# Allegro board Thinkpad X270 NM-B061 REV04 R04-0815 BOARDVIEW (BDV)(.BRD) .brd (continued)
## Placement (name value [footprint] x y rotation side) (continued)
PC405  0.047U_0201_10V6-K  [C_0201]  129.2 97.97 90 bottom
PC406  1000P_0201_25V7-K  [C_0201]  129.79 100.7 270 bottom
PC407  2200P_0201_25V7-K  [C_0201]  129.13 100.29 180 bottom
PC408  0.1U_0201_25V6-K  [C_0201]  125.13 100.65 270 top
PC409  15P_0201_25V8-J  [C_0201]  124.77 98.89 0 top
PC410  1500P_0201_25V7-K  [C_0201]  125.94 99.49 270 top
PC411  270P_0201_25V7-M  [C_0201]  125.22 96.58 0 top
PC412  1000P_0201_25V7-K  [C_0201]  125.22 98.31 0 top
PC413  1000P_0201_25V7-K  [C_0201]  120.37 92.68 0 bottom
PC414  0.022U_0201_16V6-K  [C_0201]  119.37 98.72 270 top
PC416  3300P_0201_25V7-K  [C_0201]  120.89 93.28 90 bottom
PC417  470P_0201_25V7-K  [C_0201]  122.06 96.61 180 top
PC418  0.01U_0201_6.3V7-K  [C_0201]  120.77 98.28 0 top
PC419  1000P_0201_25V7-K  [C_0201]  118.78 97.76 90 bottom
PC420  820P_0201_25V7-K  [C_0201]  119.36 98.34 270 bottom
PC421  2200P_0201_25V7-K  [C_0201]  118.3 96.56 0 bottom
PC422  470P_0201_25V7-K  [C_0201]  118.28 95.4 0 bottom
PC423  15P_0201_25V8-J  [C_0201]  119.46 95.96 90 bottom
PC424  1000P_0201_25V7-K  [C_0201]  122.39 91.92 180 bottom
PC425  0.1U_0402_25V6-K  [C_0402]  120.76 99.02 0 top
PC426  1000P_0201_25V7-K  [C_0201]  123.6 91.91 180 bottom
PC427  1000P_0201_25V7-K  [C_0201]  123.02 92.51 90 bottom
PC428  15P_0201_25V8-J  [C_0201]  123.27 96.02 270 top
PC429  15N_0201_10V6-K  [C_0201]  122.68 94.79 0 top
PC430  0.047U_0402_25V7-K  [C_0402]  126.04 92.54 180 bottom
PC431  220P_0201_25V7K  [C_0201]  125.09 96 270 top
PC432  1000P_0201_25V7-K  [C_0201]  123.88 96.01 270 top
PC433  0.01U_0201_25V6-K  [C_0201]  130.08 97.95 90 bottom
PC434  1000P_0201_25V7-K  [C_0201]  125.41 91.81 0 bottom
PC435  10U_0603_25V6-M  [C_0603]  97.75 106.84 90 top
PC436  10U_0603_25V6-M  [C_0603]  96.45 106.84 90 top
PC437  0.1U_0402_25V6  [C_0402]  94.45 106.95 90 bottom
PC438  2200P_0402_25V7-K  [C_0402]  95.36 106.95 90 top
PC439  47P_0402_50V8-J  [C_0402]  95.36 106.95 90 bottom
PC440  22U_0603_6.3V6M  [C_0603]  89.95 83.06 270 top
PC441  22U_0603_6.3V6M  [C_0603]  87.3 76.62 0 top
PC442  22U_0603_6.3V6M  [C_0603]  87.25 81.72 0 top
PC443  22U_0603_6.3V6M  [C_0603]  89.93 80.72 270 top
PC444  22U_0603_6.3V6M  [C_0603]  86.26 77.94 180 top
PC445  22U_0603_6.3V6M  [C_0603]  86.26 81.75 180 top
PC446  22U_0603_6.3V6M  [C_0603]  87.25 82.99 0 top
PC447  22U_0603_6.3V6M  [C_0603]  86.66 75.27 0 top
PC448  22U_0603_6.3V6M  [C_0603]  87.27 79.16 0 top
PC449  0.22U_0402_16V6-M  [C_0402]  94.88 104.63 180 bottom
PC450  1U_0402_6.3V6-K  [C_0402]  88.35 100.39 0 bottom
PC451  1U_0402_6.3V6-K  [C_0402]  90.23 100.42 270 bottom
PC452  22U_0603_6.3V6M  [C_0603]  85.7 75.3 180 top
PC453  1500P_0402_50V7-K  [C_0402]  88.5 110.43 0 bottom
PC454  22U_0603_6.3V6M  [C_0603]  86.26 83.02 180 top
PC455  22U_0603_6.3V6M  [C_0603]  86.26 80.48 180 top
PC456  22U_0603_6.3V6M  [C_0603]  89.02 75.27 0 top
PC457  22U_0603_6.3V6M  [C_0603]  87.25 80.43 0 top
PC458  22U_0603_6.3V6M  [C_0603]  87.27 77.89 0 top
PC459  22U_0603_6.3V6M  [C_0603]  86.26 76.67 180 top
PC460  330U_D2_2V_R9M  [C_D2]  85.71 96.56 0 bottom
PC461  22U_0603_6.3V6M  [C_0603]  89.93 78.36 270 top
PC462  22U_0603_6.3V6M  [C_0603]  86.26 79.21 180 top
PC463  10U_0603_25V6-M  [C_0603]  59.45 105.56 270 top
PC464  10U_0603_25V6-M  [C_0603]  59.8 105.18 270 bottom
PC465  10U_0603_25V6-M  [C_0603]  58.58 105.17 270 bottom
PC466  10U_0603_25V6-M  [C_0603]  57.34 105.17 270 bottom
PC467  0.1U_0402_25V6  [C_0402]  60.84 104.91 270 bottom
PC468  2200P_0402_25V7-K  [C_0402]  60.54 105.04 270 top
PC469  47P_0402_50V8-J  [C_0402]  62.06 105.07 270 top
PC470  0.22U_0402_16V6-M  [C_0402]  59.91 107.59 0 bottom
PC471  1U_0402_6.3V6-K  [C_0402]  65.76 110.66 90 bottom
PC472  22U_0603_6.3V6M  [C_0603]  83.21 75.3 180 top
PC473  22U_0603_6.3V6M  [C_0603]  74.7 75.35 0 top
PC474  22U_0603_6.3V6M  [C_0603]  78.48 75.32 180 top
PC475  22U_0603_6.3V6M  [C_0603]  74.89 83.11 270 top
PC476  22U_0603_6.3V6M  [C_0603]  79.45 75.32 0 top
PC477  22U_0603_6.3V6M  [C_0603]  83.92 81.75 180 top
PC478  22U_0603_6.3V6M  [C_0603]  78.74 76.59 180 top
PC479  22U_0603_6.3V6M  [C_0603]  73.73 76.62 180 top
PC480  1U_0402_6.3V6-K  [C_0402]  67.26 109.56 0 bottom
PC481  22U_0603_6.3V6M  [C_0603]  73.73 82.97 180 top
PC482  22U_0603_6.3V6M  [C_0603]  79.7 77.86 0 top
PC483  22U_0603_6.3V6M  [C_0603]  78.74 79.13 180 top
PC484  22U_0603_6.3V6M  [C_0603]  83.92 80.48 180 top
PC485  22U_0603_6.3V6M  [C_0603]  79.7 80.4 0 top
PC486  680P_0402_50V7K  [C_0402]  65.41 102.04 180 bottom
PC487  330U_D2_2V_R9M  [C_D2]  74.2 98.92 180 bottom
PC488  22U_0603_6.3V6M  [C_0603]  79.7 76.59 0 top
PC489  22U_0603_6.3V6M  [C_0603]  74.89 78.41 270 top
PC490  22U_0603_6.3V6M  [C_0603]  83.89 77.91 180 top
PC491  22U_0603_6.3V6M  [C_0603]  83.89 79.18 180 top
PC492  22U_0603_6.3V6M  [C_0603]  73.73 79.16 180 top
PC493  22U_0603_6.3V6M  [C_0603]  78.74 82.94 180 top
PC494  22U_0603_6.3V6M  [C_0603]  76.13 78.41 270 top
PC495  22U_0603_6.3V6M  [C_0603]  79.7 79.13 0 top
PC496  22U_0603_6.3V6M  [C_0603]  73.71 80.45 180 top
PC497  22U_0603_6.3V6M  [C_0603]  79.7 82.94 0 top
PC498  10U_0603_25V6-M  [C_0603]  97.75 106.84 90 bottom
PC499  10U_0603_25V6-M  [C_0603]  96.45 106.84 90 bottom
PC500  33U_D2_25VM_R40M  [C_D2]  59.5 99.07 0 top
PC501  33U_D2_25VM_R40M  [C_D2]  102.3 104.81 270 top
PC502  33U_D2_25VM_R40M  [C_D2]  163.15 83.1 180 bottom
PC503  33U_D2_25VM_R40M  [C_D2]  58.33 99.17 0 bottom
PC506  22U_0603_6.3V6M  [C_0603]  83.92 83.02 180 top
PC507  22U_0603_6.3V6M  [C_0603]  78.74 77.86 180 top
PC508  22U_0603_6.3V6M  [C_0603]  69.57 97.4 0 top
PC510  22U_0603_6.3V6M  [C_0603]  73.71 77.86 180 top
PC511  22U_0603_6.3V6M  [C_0603]  76.13 83.11 270 top
PC512  22U_0603_6.3V6M  [C_0603]  76.13 80.75 270 top
PC513  22U_0603_6.3V6M  [C_0603]  74.89 80.75 270 top
PC514  22U_0603_6.3V6M  [C_0603]  83.89 76.64 180 top
PC515  22U_0603_6.3V6M  [C_0603]  79.7 81.67 0 top
PC516  22U_0603_6.3V6M  [C_0603]  78.74 80.4 180 top
PC517  22U_0603_6.3V6M  [C_0603]  78.74 81.67 180 top
PC522  10U_0603_25V6-M  [C_0603]  136.81 85.59 270 bottom
PC523  10U_0603_25V6-M  [C_0603]  137.75 86.94 90 bottom
PC524  0.1U_0402_25V6  [C_0402]  135.76 85.46 270 bottom
PC525  2200P_0402_25V7-K  [C_0402]  135.82 86.91 90 bottom
PC526  47P_0402_50V8-J  [C_0402]  136.68 86.91 90 bottom
PC527  0.22U_0402_16V6-M  [C_0402]  136.07 83.25 180 bottom
PC528  1U_0402_6.3V6-K  [C_0402]  130 80.26 0 bottom
PC529  1U_0402_6.3V6-K  [C_0402]  135.13 81.42 0 bottom
PC530  22U_0603_6.3V6M  [C_0603]  117 85.31 270 bottom
PC531  22U_0603_6.3V6M  [C_0603]  116.95 78.7 90 bottom
PC532  22U_0603_6.3V6M  [C_0603]  92.45 82.21 180 top
PC533  22U_0603_6.3V6M  [C_0603]  92.45 80.94 180 top
PC534  22U_0603_6.3V6M  [C_0603]  92.45 78.4 180 top
PC535  22U_0603_6.3V6M  [C_0603]  92.45 79.67 180 top
PC536  680P_0402_50V7K  [C_0402]  130.13 83.33 90 top
PC537  22U_0603_6.3V6M  [C_0603]  118.22 78.7 90 bottom
PC538  22U_0603_6.3V6M  [C_0603]  118.22 85.31 270 bottom
PC539  22U_0603_6.3V6M  [C_0603]  115.73 78.7 90 bottom
PC540  22U_0603_6.3V6M  [C_0603]  115.78 85.33 270 bottom
PC712  0.1U_0402_25V6  [C_0402]  140.42 101.1 270 bottom
PC713  10U_0603_25V6-M  [C_0603]  143.57 101.88 270 bottom
PC714  10U_0603_25V6-M  [C_0603]  142.35 101.88 270 bottom
PC715  2200P_0402_25V7-K  [C_0402]  139.56 101.1 270 bottom
PC716  2.2U_0603_10V6-K  [C_0603]  144.98 104.81 0 bottom
PC717  0.1U_0402_16V7-K  [C_0402]  151.19 99.48 0 bottom
PC718  0.1U_0402_6.3V7-K  [C_0402]  139.02 90.62 270 bottom
PC719  22U_0603_6.3V6M  [C_0603]  138.57 96.95 270 bottom
PC720  22U_0603_6.3V6M  [C_0603]  140.11 89.31 90 bottom
PC721  22U_0603_6.3V6M  [C_0603]  137.74 98.56 180 bottom
PC722  22U_0603_6.3V6M  [C_0603]  139.79 96.98 270 bottom
PC723  2200P_0402_25V7-K  [C_0402]  137.5 96.1 90 bottom
PC724  22U_0603_6.3V6M  [C_0603]  141.1 97.58 270 bottom
PC737  0.1U_0402_25V6-K  [C_0402]  133.38 73.62 90 bottom
PC738  10U_0603_10V  [C_0603]  134.43 73.58 90 bottom
PC739  0.1U_0402_25V6  [C_0402]  132.04 78.24 180 bottom
PC740  22U_0603_6.3V6-M  [C_0603]  134.65 78.62 90 bottom
PC741  22P_0402_50V  [C_0402]  133.51 71.56 0 bottom
PC743  22U_0603_6.3V6-M  [C_0603]  133.4 78.62 90 bottom
PC745  680P_0402_50V  [C_0402]  136.41 71.74 0 top
PC746  2200P_0402_25V7-K  [C_0402]  132.04 79.11 180 bottom
PC756  2200P_0402_25V7-K  [C_0402]  147.56 64.02 270 bottom
PC776  0.01U_0402_25V7-K  [C_0402]  148.52 104.56 90 bottom
PC783  2200P_0402_25V7-K  [C_0402]  158.45 64.17 180 bottom
PC784  10U_0603_10V  [C_0603]  158.72 63.13 180 bottom
PC785  22U_0603_6.3V6-M  [C_0603]  146.48 66.34 90 bottom
PC786  0.1U_0402_25V6  [C_0402]  147.55 66.89 90 bottom
PC787  680P_0402_50V7K  [C_0402]  143.06 97.17 90 bottom
PC788  68P_0402_50V8J  [C_0402]  138.67 101.1 270 bottom
PC789  0.1U_0603_25V7K  [C_0603]  151.85 96.43 270 bottom
PC790  47P_0402_50V8-J  [C_0402]  141.31 101.08 270 bottom
PC791  10U_0603_10V  [C_0603]  158.7 63.08 180 top
PC792  0.1U_0402_6.3V7-K  [C_0402]  152.16 100.37 180 bottom
PC793  22U_0603_6.3V6-M  [C_0603]  146.49 64.44 270 bottom
PC794  0.1U_0402_10V  [C_0402]  138.24 69.99 180 bottom
PC795  2200P_0402_25V7-K  [C_0402]  132.52 73.49 90 bottom
PC801  0.1U_0402_25V6-K  [C_0402]  158.43 64.12 180 top
PC802  680P_0402_50V  [C_0402]  156.68 64.2 180 bottom
PC803  22P_0402_50V  [C_0402]  160.54 66.38 90 bottom
PD1  -  [1SS400CMT2R_VMN2M2]  141.45 112.9 270 top
PD2  -  [1SS400CMT2R_VMN2M2]  143.94 112.9 90 top
PD4  -  [RB751V-40_SOD323-2]  109.63 104.84 0 top
PD5  -  [AZ5425-01F_DFN1006P2E2]  112.23 106.23 0 top
PD7  ESD9B5.0ST5G SOD-923  [DF2S6P8UFS_1-1L1A2]  231.99 107.26 90 top
PD8  ESD9B5.0ST5G SOD-923  [DF2S6P8UFS_1-1L1A2]  234.43 107.28 90 top
PD9  ESD9B5.0ST5G SOD-923  [DF2S6P8UFS_1-1L1A2]  235.49 107.31 90 top
PD10  -  [DAN222MGT2L_VMD3]  166.19 88.79 90 top
PD11  -  [DAN222MGT2L_VMD3]  149.23 112.51 270 top
PD12  -  [DAN222MGT2L_VMD3]  184.08 63.19 180 bottom
PD13  -  [DAN222MGT2L_VMD3]  264.47 97.1 270 top
PD14  -  [DAN222MGT2L_VMD3]  177.91 84.01 0 bottom
PD15  -  [DAN222MGT2L_VMD3]  180.13 64.44 0 bottom
PD16  -  [DAN222MGT2L_VMD3]  182.48 62.12 0 bottom
PD17  -  [DAN222MGT2L_VMD3]  263.52 95.8 0 top
PD18  -  [DAN222MGT2L_VMD3]  261.84 95.8 0 top
PD30  EDZVT2R5.1B  [RB520SM-30T2R_EMD2-2]  158.01 87.49 0 top
PD31  -  [DAN222MGT2L_VMD3]  162.74 87.06 180 top
PD32  RB161SS-30T2R  [RB521CS-30GT2RA_VMN2-2]  162.38 91.91 90 top
PD102  RB521CM_30  [RB521CS-30GT2RA_VMN2-2]  191.03 66.22 90 top
PD301  RB521CM_30  [RB521CS-30GT2RA_VMN2-2]  120.11 61.1 0 bottom
PD701  RB751V-40  [RB751V-40_SOD323-2]  140.12 69.38 180 top
PF2  7A_24V_0429007.WRMLHF  [F_S1206-H-5P0A]  130.87 111.95 0 top
PF3  10A_32V_0501010.WR  [F_TR-3216FF10-R]  189.87 60.94 90 bottom
PF4  10A_32V_0501010.WR  [F_TR-3216FF10-R]  226.81 101.49 180 top
PF5  0.5A_32V_ERBRD0R50X  [F_ERBRD0R50X]  166.24 91.08 270 top
PF6  0.5A_32V_ERBRD0R50X  [F_ERBRD0R50X]  146.21 112.86 0 top
PF7  0.5A_32V_ERBRD0R50X  [F_ERBRD0R50X]  186.81 62.39 180 bottom
PF8  0.5A_32V_ERBRD0R50X  [F_ERBRD0R50X]  261.14 96.77 0 top
PF9  0.5A_32V_ERBRD0R50X  [F_ERBRD0R50X]  176.59 85.97 270 bottom
PF11  0.5A_32V_ERBRD0R50X  [F_ERBRD0R50X]  156.24 96.54 0 top
PJ1  MOLEX_78048-0543  [MOLEX_78048-0543_5P-T]  109.91 103.98 90 bottom
PJ2  JST_SM05BLBTAKSTDN2T-HF  [JST_SM05BLBTAKSTDN2T-HF_5P-T]  189.18 58.93 180 bottom
PJ3  FOX_BBP27BY-B4801-7H  [FOX_BBP27BY-B4801-7H_7P-T]  225.6 104.31 0 bottom
PJ4  -  [JUMP_43X79]  14.53 71.9 180 bottom
PJ201  -  [JUMP_43X79]  174.33 84.21 90 bottom
PJ202  -  [JUMP_43X79]  145.55 85.08 0 bottom
PJ203  -  [JUMP_43X118]  145.14 76.2 270 bottom
PJ204  -  [JUMP_43X118]  176.54 70.2 90 bottom
PJ301  -  [JUMP_43X79]  125.59 57.59 180 bottom
PJ302  -  [JUMP_43X118]  88.78 58.76 270 top
PJ303  -  [JUMP_43X118]  91.4 59.73 0 top
PJ304  -  [JUMP_43X39]  121.09 68.42 0 bottom
PJ701  -  [JUMP_43X79]  136.53 100.7 0 bottom
PJ702  -  [JUMP_43X118]  135.3 95.95 0 bottom
PJ703  -  [JUMP_43X118]  135.3 91.88 0 bottom
PJ711  -  [JUMP_43X79]  130.84 76.34 0 bottom
PJ712  -  [JUMP_43X79]  131.51 73.34 180 bottom
PJ715  -  [JUMP_43X79]  160.05 63.99 0 bottom
PJ716  -  [JUMP_43X79]  144.13 65.26 0 bottom
PL1  1.0UH_DFE252010F-100M=P2_20%  [CYNTE_HMMB25201T-1R0MSR_2P]  158.09 93.01 0 top
PL101  2.2UH_CMLE063T-2R2MS_10A_20%  [CYNTE_PCMB063T-2R2MS_2P]  189.37 77.2 90 bottom
PL102  BLM18KG300TN1D  [TDK_MPZ1608S300AT_2P]  147.71 109.8 0 top
PL103  BLM18KG300TN1D  [TDK_MPZ1608S300AT_2P]  147.7 108.53 0 top
PL201  2.2UH_PCMB063T-2R2MS_8A_20%  [CYNTE_PCMB063T-2R2MS_2P]  168.51 71.92 90 bottom
PL202  2.2UH_PCMB063T-2R2MS_8A_20%  [CYNTE_PCMB063T-2R2MS_2P]  150.71 77.35 270 bottom
PL301  1UH_PCMC063T-1R0MN_11A_20%  [CYNTE_PCMC063T-1R0MN_2P]  111.77 58.13 270 bottom
PL401  0.15UH_CMLE063T-R15MS0R907_38A_20%  [CYNTE_PCME063T-R15MS0R907_2P]  84.33 107.01 270 bottom
PL402  0.15UH_CMLE063T-R15MS0R907_38A_20%  [CYNTE_PCME063T-R15MS0R907_2P]  69.57 105.3 0 bottom
PL404  0.47UH_PCMB063T-R47MS3R675_18A_20%  [CYNTE_PCMB063T-R47MS3R675_2P]  126.96 82.92 180 bottom
PL405  BLM18KG300TN1D  [TDK_MPZ1608S300AT_2P]  96.91 103.85 90 bottom
PL406  BLM18KG300TN1D  [TDK_MPZ1608S300AT_2P]  98.13 103.85 90 bottom
PL407  BLM18KG300TN1D  [TDK_MPZ1608S300AT_2P]  59.42 108.38 270 top
PL408  BLM18KG300TN1D  [TDK_MPZ1608S300AT_2P]  58.28 109 270 bottom
PL410  BLM18KG300TN1D  [TDK_MPZ1608S300AT_2P]  138.03 83.87 90 bottom
PL702  1.0UH_PCMC063T-1R0MN_11A_20%  [CYNTE_PCMB063T-1R0MS_2P]  149.18 93.13 180 bottom
PL703  1UH_PH041H-1R0MS_3.8A_20%  [CYNTE_PH041H-1R0MS_2P]  139.76 77.61 180 bottom
PL704  1UH_PH041H-1R0MS_3.8A_20%  [CYNTE_PH041H-1R0MS_2P]  152.82 65.54 180 bottom
PQ2  AON7409  [SI7121DN-T1-GE3_POWERPAK-8-5]  159.48 100.73 270 top
PQ5  LSK3541G1ET2L  [2SK3541_VMT3]  133.43 106.98 180 top
PQ6  AON7409  [SI7121DN-T1-GE3_POWERPAK-8-5]  135.71 112.51 270 top
PQ7  AON7409  [SI7121DN-T1-GE3_POWERPAK-8-5]  142.97 109.56 90 top
PQ8  -  [DTA014EMT2L_VMT3]  131.56 106.93 180 top
PQ9  LSK3541G1ET2L  [2SK3541_VMT3]  130.12 107.92 270 top
PQ10  LSK3541G1ET2L  [2SK3541_VMT3]  135.59 107 180 top
PQ11  NTJD5121NT1G 2N SC88-6  [2N7002KDWH_SOT363-6]  108.38 108.28 180 top
PQ12  AON7466  [SIS406DN-T1-GE3_PAK1212-8-5]  19.22 73.46 90 top
PQ13  AON7466  [SIS406DN-T1-GE3_PAK1212-8-5]  15.71 69.01 0 top
PQ14  AON6380  [TPCA8059-H_PPAK56-8-5]  191.03 75.99 180 top
PQ15  -  [2N7002WT1G_SC-70-3]  19.28 71.69 180 bottom
PQ17  AON7466  [SIS406DN-T1-GE3_PAK1212-8-5]  187.71 63.58 180 bottom
PQ18  AON7409  [SI7121DN-T1-GE3_POWERPAK-8-5]  189.48 65.11 90 bottom
PQ19  AON7466  [SIS406DN-T1-GE3_PAK1212-8-5]  224.39 99.41 180 top
PQ20  AON7409  [SI7121DN-T1-GE3_POWERPAK-8-5]  226.51 98.44 270 top
PQ21  -  [SSM6J402TU_UF6]  181.61 64.22 90 bottom
PQ22  -  [DTC015EMT2L_VMT3]  178.19 66.01 0 bottom
PQ23  -  [SSM6J402TU_UF6]  262.08 93.61 270 top
PQ24  -  [DTC015EMT2L_VMT3]  262.08 90.87 270 top
PQ37  -  [AON6248_DFN8-5]  18.31 66.77 180 top
PQ41  LSK3541G1ET2L  [2SK3541_VMT3]  137.79 108.83 90 top
PQ42  -  [2SCR512P5T100_MPT3]  255.2 89.2 90 top
PQ103  AON7409  [SI7121DN-T1-GE3_POWERPAK-8-5]  203.54 93.15 270 top
PQ104  LSK3541G1ET2L  [2SK3541_VMT3]  199.77 88.2 270 top
PQ105  LSK3541G1ET2L  [2SK3541_VMT3]  203.63 66.66 270 top
PQ106  LSK3541G1ET2L  [2SK3541_VMT3]  205.38 69.51 270 top
PQ107  LSK3541G1ET2L  [2SK3541_VMT3]  202.23 68.26 90 top
PQ108  AON7409  [SI7121DN-T1-GE3_POWERPAK-8-5]  196.56 84.7 270 top
PQ109  LSK3541G1ET2L  [2SK3541_VMT3]  197.55 81.06 90 top
PQ110  AON6380  [TPCA8059-H_PPAK56-8-5]  187.33 74.23 0 bottom
PQ111  AON6380  [TPCA8059-H_PPAK56-8-5]  181.01 80.89 0 bottom
PQ112  AON7380  [SIS406DN-T1-GE3_PAK1212-8-5]  191.96 85.47 270 top
PQ113  AON7380  [SIS406DN-T1-GE3_PAK1212-8-5]  190.11 87.44 180 top
PQ201  AON7410 1N DFN  [AON7408L_DFN8-5]  170.56 80.66 90 bottom
PQ202  AON7410 1N DFN  [AON7408L_DFN8-5]  149.69 79.98 180 bottom
PQ203  AON7534 1N DFN  [AON7408L_DFN8-5]  166.23 83.46 0 bottom
PQ204  AON7534 1N DFN  [AON7408L_DFN8-5]  151.5 82.78 0 bottom
PQ301  AON7410 1N DFN  [AON7408L_DFN8-5]  116.01 56.73 90 bottom
PQ302  AON7534 1N DFN  [AON7408L_DFN8-5]  118.81 55.05 270 bottom
PR1  200K_0201_5%  [R_0201]  158.04 97.58 270 top
PR2  100K_0201_5%  [R_0201]  159.23 96.97 180 top
PR3  100_0201_5%  [R_0201]  158.65 97.55 0 top
PR6  24_1210_1%  [R_1210]  263.07 88.41 0 top
PR7  20_1210_1%  [R_1210]  258.17 90.85 270 top
PR8  200K_0201_5%  [R_0201]  134.65 109.42 90 top
PR9  100_0201_5%  [R_0201]  135.3 109.33 0 top
PR10  100_0201_5%  [R_0201]  144.58 112.06 180 top
PR11  270_0201_5%  [R_0201]  131.62 106.21 0 top
PR12  200K_0201_5%  [R_0201]  144.58 111.5 180 top
PR13  100K_0201_5%  [R_0201]  134.65 106.21 180 top
PR14  470K_0402_5%  [R_0402]  136.86 108.17 270 top
PR15  750_0201_1%  [R_0201]  109.28 106.12 90 top
PR16  0_0201_5%  [R0201_SHORT]  109.25 108.27 270 top
PR17  10K_0402_1%  [R_0402]  110.17 106.23 0 top
PR18  1M_0201_5%  [R_0201]  105.61 108.6 0 top
PR19  1M_0201_5%  [R_0201]  106.19 108.01 180 top
PR20  1M_0201_5%  [R_0201]  19.5 68.34 180 top
PR21  0_0201_5%  [R_0201]  19.5 68.97 180 top
PR22  0_0201_5%  [R_0201]  20.91 76.08 180 top
PR23  1M_0201_5%  [R_0201]  21.03 75.46 270 top
PR24  750_0603_1%  [R_0603]  253.44 87.11 0 top
PR25  0.005_1206_1%  [R_1206]  20.66 72.42 0 top
PR26  6.19K_0201_1%  [R_0201]  182.61 61.15 180 bottom
PR27  100_0201_5%  [R_0201]  186.57 60.6 90 bottom
PR28  100_0201_5%  [R_0201]  185.96 60.6 90 bottom
PR29  510K_0201_5%  [R_0201]  188.94 65.14 180 top
PR30  100_0201_5%  [R_0201]  189.26 65.79 90 top
PR31  100K_0201_5%  [R_0201]  184.57 64.9 270 bottom
PR32  150K_0201_5%  [R_0201]  190.13 65.14 180 top
PR33  6.19K_0201_1%  [R_0201]  236.33 106.83 90 top
PR34  100_0201_5%  [R_0201]  232.88 106.83 90 top
PR35  100_0201_5%  [R_0201]  233.54 106.83 90 top
PR36  510K_0201_5%  [R_0201]  225.29 95.21 180 top
PR37  100_0201_5%  [R_0201]  225.9 95.21 0 top
PR38  100K_0201_5%  [R_0201]  221.17 98.98 90 top
PR39  150K_0201_5%  [R_0201]  226.49 94.6 180 top
PR40  470K_0201_5%  [R_0201]  183.03 67.3 0 bottom
PR41  100_0201_5%  [R_0201]  182.15 66.4 180 bottom
PR42  4.7K_0201_5%  [R_0201]  181.55 66.98 0 bottom
PR43  470K_0201_5%  [R_0201]  264.24 91.17 0 top
PR44  100_0201_5%  [R_0201]  263.61 91.17 180 top
PR45  4.7K_0201_5%  [R_0201]  263.02 90.56 0 top
PR46  2K_0402_5%  [R_0402]  4.57 66.19 90 bottom
PR77  2.7K_0805_5%  [R_0805]  156.69 90.71 270 top
PR78  56.2K_0201_1%  [R_0201]  161.65 87.85 180 top
PR79  10K_0201_1%  [R_0201]  160.43 88.45 180 top
PR82  169K_0402_1%  [R_0402]  15.55 74.36 0 bottom
PR83  24.3K_0402_1%  [R_0402]  22.02 73.37 0 bottom
PR84  3.9K_0402_5%  [R_0402]  15.55 73.47 0 bottom
PR87  100K_0402_1%  [R_0402]  2.54 64.3 0 bottom
PR88  100K_0402_1%  [R_0402]  3.58 66.08 180 bottom
PR89  27.4K_0402_1%  [R_0402]  2.47 63.42 0 bottom
PR90  0_0402_5%  [R_0402]  2.54 65.19 0 bottom
PR91  0_0201_5%  [R0201_SHORT]  21.65 70.52 90 top
PR92  0_0201_5%  [R0201_SHORT]  22.21 70.52 90 top
PR95  0.005_1206_1%  [R_1206]  12.37 64.88 270 top
PR96  47_0402_5%  [R_0402]  11.05 61.71 0 bottom
PR97  10_0402_1%  [R_0402]  6.35 67.12 270 bottom
PR98  100K_0402_1%  [R_0402]  7.23 66.21 90 bottom
PR99  26.1K_0402_1%  [R_0402]  5.45 67.1 270 bottom
PR101  100K_0201_1%  [R_0201]  203.62 72.14 270 top
PR102  0_0603_5%  [R_0603]  195.61 68.99 90 top
PR103  0_0603_5%  [R_0603]  194.39 68.99 90 top
PR133  10_0201_1%  [R_0201]  198.43 71.71 270 top
PR134  40.2K_0201_1%  [R_0201]  203.56 77.95 270 top
PR135  100K_0201_1%  [R_0201]  201.39 68.19 180 top
PR136  10_0603_5%  [R_0603]  203.32 69.68 180 top
PR137  0_0402_5%  [R_0402]  195.79 77.99 90 top
PR138  10_0201_1%  [R_0201]  197.44 71.71 270 top
PR139  0_0201_5%  [R_0201]  200.33 80.71 0 top
PR140  10K_0201_5%  [R_0201]  200.21 69.35 90 top
PR141  0_0201_5%  [R_0201]  202.61 73.06 0 top
PR142  75_0201_5%  [R_0201]  203.76 74 180 top
PR144  20K_0201_1%  [R_0201]  201.6 79.34 0 top
PR145  100K_0201_1%  [R_0201]  201.01 79.18 180 top
PR146  0_0402_5%  [R_0402]  204.17 75.68 180 top
PR147  280K_0201_1%  [R_0201]  201.39 68.77 180 top
PR148  0_0402_5%  [R_0402]  204.17 74.76 180 top
PR149  0_0402_5%  [R_0402]  194.39 74.41 270 top
PR150  20K_0201_1%  [R_0201]  205.36 73.06 180 top
PR151  0.01_1206_LE_1%  [R_1206_LE]  208 92.06 0 top
PR152  100K_0201_1%  [R_0201]  204.95 77.66 0 top
PR153  56_0402_5%  [R_0402]  179.56 79.46 90 bottom
PR154  71.5K_0201_1%  [R_0201]  200.43 78.63 0 top
PR155  0_0201_5%  [R_0201]  200.33 80.15 0 top
PR156  56_0402_5%  [R_0402]  189.32 87.03 0 bottom
PR157  0_0201_5%  [R_0201]  202.35 72.14 0 top
PR158  0.01_1206_LE_1%  [R_1206_LE]  182.6 70.93 0 bottom
PR160  0_0402_5%  [R_0402]  193.57 74.41 270 bottom
PR161  0_0402_5%  [R_0402]  192.27 82.12 180 top
PR162  0_0201_5%  [R_0201]  203.81 78.6 0 top
PR163  100K_0201_5%  [R_0201]  204.24 70.65 0 top
PR164  100K_0201_5%  [R_0201]  205.37 68.35 270 top
PR165  1K_0201_1%  [R_0201]  196.72 71.71 270 top
PR166  0_0201_5%  [R_0201]  203.74 76.72 180 top
PR167  1M_0201_5%  [R_0201]  204.14 67.78 0 top
PR168  10K_0201_5%  [R_0201]  200.78 69.37 90 top
PR169  510K_0201_5%  [R_0201]  195.48 82 270 top
PR170  0_0402_5%  [R_0402]  203.31 89.83 0 top
PR171  100_0201_5%  [R_0201]  196.13 81.57 0 top
PR172  150K_0201_5%  [R_0201]  196.72 80.99 180 top
PR179  1K_0201_5%  [R_0201]  200.57 88.65 270 top
PR190  14.3K_0201_1%  [R_0201]  204.95 77.08 0 top
PR196  0_0201_5%  [R_0201]  198.23 68.67 270 top
PR197  0_0201_5%  [R_0201]  197.66 68.67 270 top
PR208  0_0402_5%  [R0402_SHORT]  156.02 75.55 90 bottom
PR209  0_0402_5%  [R0402_SHORT]  163.08 76.54 270 bottom
PR210  150K_0201_1%  [R_0201]  161.63 70.83 180 bottom
PR211  130K_0201_1%  [R_0201]  157.59 70.8 0 bottom
PR212  4.7_0603_5%  [R_0603]  167.98 81.89 270 top
PR213  4.7_0603_5%  [R_0603]  154.97 80.17 270 bottom
PR214  0_0201_5%  [R0201_SHORT]  158.81 70.8 90 bottom
PR215  0_0201_5%  [R0201_SHORT]  160.44 70.83 90 bottom
PR216  200_0402_1%  [R_0402]  163.12 74 0 bottom
PR217  15K_0201_1%  [R_0201]  163.12 73.16 0 bottom
PR218  13.7K_0201_1%  [R_0201]  156.27 72.83 180 bottom
PR219  200K_0201_1%  [R_0201]  158.18 71.39 180 bottom
PR220  100K_0201_1%  [R_0201]  161.63 71.41 180 bottom
PR221  0_0201_5%  [R0201_SHORT]  155.67 73.47 0 bottom
PR222  0_0201_5%  [R0201_SHORT]  156.26 74.05 180 bottom
PR301  0_0201_5%  [R0201_SHORT]  120.81 64.81 0 bottom
PR302  0_0201_5%  [R_0201]  120.57 62.45 0 bottom
PR303  64.9K_0201_1%  [R_0201]  124.52 65.39 180 top
PR304  1K_0201_5%  [R_0201]  123.94 66 0 top
PR305  100K_0201_1%  [R_0201]  121.29 65.65 0 bottom
PR306  0_0201_5%  [R0201_SHORT]  120.57 61.89 0 bottom
PR307  13K_0201_1%  [R_0201]  128 65.32 0 top
PR308  25.5K_0201_1%  [R_0201]  128.94 63.97 90 bottom
PR309  0_0402_5%  [R0402_SHORT]  121.93 61.56 270 bottom
PR311  4.7_0603_5%  [R_0603]  117.38 51.5 180 bottom
PR312  0_0402_5%  [R0402_SHORT]  126.15 64.66 180 top
PR401  100_0201_5%  [R_0201]  131.59 96.77 180 bottom
PR402  1K_0402_5%  [R_0402]  118.35 101.64 270 bottom
PR403  2_0603_5%  [R_0603]  118.36 102.73 0 bottom
PR404  47_0201_5%  [R_0201]  131.58 95.65 180 bottom
PR405  10K_0201_5%  [R_0201]  129.31 93.08 180 bottom
PR406  0_0201_5%  [R0201_SHORT]  129.32 93.66 180 bottom
PR407  51_0201_5%  [R_0201]  129.85 95.65 180 bottom
PR408  10_0201_5%  [R_0201]  129.86 96.81 180 bottom
PR409  0_0201_5%  [R0201_SHORT]  129.86 96.24 180 bottom
PR410  75_0201_5%  [R_0201]  129.53 97.38 0 bottom
PR411  3K_0402_1%  [R_0402]  130.89 97.91 90 bottom
PR412  20K_0402_1%  [R_0402]  121.94 94.82 90 top
PR413  10K_0201_1%  [R_0201]  131.65 98.14 90 bottom
PR414  2.21K_0201_1%  [R_0201]  129.18 100.87 180 bottom
PR415  1K_0201_1%  [R_0201]  129.14 99.73 180 bottom
PR416  0_0201_5%  [R0201_SHORT]  125.72 100.66 270 top
PR417  61.9K_0201_1%  [R_0201]  93.54 100.57 180 bottom
PR418  2.49K_0201_1%  [R_0201]  124.77 99.48 0 top
PR419  35.7K_0201_1%  [R_0201]  125.22 97.73 0 top
PR420  68.1K_0201_1%  [R_0201]  125.22 97.15 0 top
PR421  7.5K_0201_1%  [R_0201]  118.72 98.73 180 top
PR423  10_0201_1%  [R_0201]  118.14 98.11 0 top
PR424  1K_0201_1%  [R_0201]  120.3 93.28 90 bottom
PR425  24.9K_0201_1%  [R_0201]  122.07 97.21 180 top
PR427  68K_0402_1%  [R_0402]  117.99 98.49 180 bottom
PR428  562_0201_1%  [R_0201]  119.45 94.77 90 bottom
PR429  73.2K_0201_1%  [R_0201]  118.14 97.17 180 bottom
PR430  165K_0201_1%  [R_0201]  117.55 97.76 0 bottom
PR432  4.75K_0201_1%  [R_0201]  118.86 95.97 180 bottom
PR433  12.4K_0201_1%  [R_0201]  119.36 97.17 180 bottom
PR434  49.9_0201_1%  [R_0201]  118.86 94.78 180 bottom
PR435  2.8K_0201_1%  [R_0201]  122.43 92.54 90 bottom
PR436  0_0201_5%  [R0201_SHORT]  119.33 99.99 180 bottom
PR437  61.9K_0201_1%  [R_0201]  62.4 111.9 180 bottom
PR438  1K_0201_1%  [R_0201]  123.6 92.51 90 bottom
PR439  3K_0402_1%  [R_0402]  127.47 92.54 270 bottom
PR440  10K_0201_1%  [R_0201]  126.76 92.54 270 bottom
PR441  1.5K_0201_1%  [R_0201]  122.68 96.02 270 top
PR442  31.6K_0201_1%  [R_0201]  124.46 96 270 top
PR443  110K_0201_1%  [R_0201]  125.69 95.99 270 top
PR444  24K_0201_5%  [R_0201]  121.57 101.43 0 top
PR445  24K_0201_5%  [R_0201]  121.57 100.85 0 top
PR446  49.9K_0201_1%  [R_0201]  122.74 100.65 270 top
PR447  100K_0201_1%  [R_0201]  123.33 100.05 90 top
PR448  15.8K_0201_1%  [R_0201]  123.91 100.65 270 top
PR449  10K_0201_1%  [R_0201]  124.55 100.65 270 top
PR450  0_0201_5%  [R0201_SHORT]  119.21 99.33 180 bottom
PR451  2_0603_5%  [R_0603]  88.66 101.43 0 bottom
PR452  2.21K_0201_1%  [R_0201]  127.48 101.91 180 bottom
PR453  3.9_0402_1%  [R_0402]  93.96 103.64 0 bottom
PR455  4.7_0603_5%  [R_0603]  87.46 110.4 270 bottom
PR456  3.9_0402_1%  [R_0402]  60.89 108.8 180 bottom
PR457  2_0603_5%  [R_0603]  68.11 111.09 180 bottom
PR461  4.7_0603_5%  [R_0603]  66.33 102.12 0 bottom
PR462  0_0402_5%  [R0402_SHORT]  119.54 100.9 180 top
PR463  0_0201_5%  [R0201_SHORT]  79.75 103.18 270 bottom
PR464  0_0201_5%  [R0201_SHORT]  80.35 103.18 270 bottom
PR465  0_0201_5%  [R0201_SHORT]  72.2 109.64 90 bottom
PR466  0_0201_5%  [R0201_SHORT]  72.78 109.64 90 bottom
PR467  0_0201_5%  [R0201_SHORT]  124.65 86.72 90 bottom
PR468  0_0201_5%  [R0201_SHORT]  123 86.77 90 bottom
PR469  2_0603_5%  [R_0603]  130.33 80.92 180 top
PR470  3.9_0402_1%  [R_0402]  135.15 82.31 0 bottom
PR473  2.8K_0201_1%  [R_0201]  121.81 92.55 90 bottom
PR474  0_0201_5%  [R_0201]  129.87 94.5 180 bottom
PR475  0_0201_5%  [R0201_SHORT]  129.26 95.08 0 bottom
PR476  4.7_0603_5%  [R_0603]  129.06 83.21 90 top
PR477  0_0201_5%  [R0201_SHORT]  128.7 92.5 270 bottom
PR708  0_0201_5%  [R_0201]  147.75 104.28 180 bottom
PR709  0_0402_5%  [R0402_SHORT]  148.03 97.57 0 bottom
PR718  0_0201_5%  [R0201_SHORT]  138.95 70.71 270 bottom
PR721  10K_0201_1%  [R_0201]  134.97 70.78 0 bottom
PR722  4.7_0603_5%  [R_0603]  138.22 71.59 0 top
PR723  20K_0201_1%  [R_0201]  133.8 70.78 0 bottom
PR724  31.6K_0201_1%  [R_0201]  159.72 66.8 90 bottom
PR738  100K_0201_5%  [R_0201]  151.76 98.16 180 bottom
PR749  0_0201_5%  [R0201_SHORT]  151.23 97.55 0 bottom
PR750  0_0201_5%  [R0201_SHORT]  155.27 68.44 0 top
PR751  100K_0201_5%  [R_0201]  160.63 68.08 0 bottom
PR753  10K_0201_1%  [R_0201]  161.38 67.41 270 bottom
PR755  0_0201_5%  [R0201_SHORT]  151.76 98.74 180 bottom
PR760  4.7_0603_5%  [R_0603]  144.04 97.29 0 bottom
PR761  0_0201_5%  [R_0201]  149.56 97.36 90 bottom
PR762  1M_0201_1%  [R_0201]  138.35 70.73 180 bottom
PR765  210K_0402_1%  [R_0402]  152.16 101.28 180 bottom
PR766  210K_0402_1%  [R_0402]  151.39 103.06 270 bottom
PR801  1M_0201_1%  [R_0201]  155.22 66.94 0 top
PR802  0.1U_0402_10V  [C_0402]  155.1 67.68 0 top
PR803  4.7_0603_5%  [R_0603]  156.13 63.16 180 bottom
PRT401  MURAT_NCP15WF104F03RC  [R_0402-TH]  80.32 100.03 90 bottom
PRT402  MURAT_NCP15WF104F03RC  [R_0402-TH]  93.52 101.41 180 bottom
PRT403  MURAT_NCP15WM224J03RC  [R_0402-TH]  74.96 109.33 0 bottom
PRT404  MURAT_NCP15WF104F03RC  [R_0402-TH]  62.39 110.68 180 bottom
PRT405  MURAT_NCP15WF104F03RC  [R_0402-TH]  123.83 87.96 270 bottom
PU4  -  [APL3542AQBI-TRG_TDFN10_3X3]  8.19 64.78 180 bottom
PU5  -  [TPS61041DRVR_SON6_2X2]  158.33 90.6 90 top
PU6  -  [NCP431AISNT1G_SOT23-3]  265.46 85.21 90 top
PU101  -  [BQ25700RSNR_QFN32_4X4]  198.02 73.47 0 top
PU201  TPS51285B-1RUKR_WQFN20_3X3  [TPS51285BRUKR_WQFN20_3X3]  160.41 73.39 90 bottom
PU301  -  [TPS51716RUKR_WQFN20_3X3]  123.93 65.55 0 bottom
PU401  NCP81218MNTXG_QFN48_6X6  [NCP81208MNTXG_QFN48_6X6]  121.32 95.74 0 bottom
PU402  -  [NCP81382MNTXG_QFN39-31_6X4]  91.79 102.83 90 bottom
PU403  -  [NCP81382MNTXG_QFN39-31_6X4]  63.1 109.4 270 bottom
PU405  -  [NCP81382MNTXG_QFN39-31_6X4]  132.85 81.6 90 bottom
PU701  RT8068AZQW  [RT8068AZQW_WDFN10_3X3]  155.43 65.33 90 bottom
PU702  TPS51367RVER  [TPS51367RVER_QFN28_3P5X4P5]  148.8 99.42 180 bottom
PU706  RT8068AZQW  [RT8068AZQW_WDFN10_3X3]  139 73.88 270 bottom
Q1  -  [TPCF8002_2-3U1A]  140.61 84.13 90 bottom
Q4  -  [MMBT3904_SOT23-3]  218.01 59.43 270 top
Q5  LSK3541G1ET2L 1N VMT3  [2SK3541_VMT3]  219.93 53.25 90 top
Q7  LSK3541G1ET2L 1N VMT3  [2SK3541_VMT3]  242.54 70.73 270 top
Q8  -  [DTC115EMGT2L_VMT3]  218.42 76.57 180 top
Q9  -  [2SC5658GT2LR_VMT3]  92.38 99.71 90 bottom
Q10  -  [2SC5658GT2LR_VMT3]  178.39 83.17 180 bottom
Q11  -  [2SC5658GT2LR_VMT3]  18.01 19.83 90 bottom
Q12  -  [2SC5658GT2LR_VMT3]  244.31 48.07 270 bottom
Q13  -  [2SC5658GT2LR_VMT3]  204.58 47.94 0 bottom
Q14  -  [RW1E014SNT2R_WEMT6]  164.18 66.32 270 bottom
Q16  LSK3541G1ET2L 1N VMT3  [2SK3541_VMT3]  244.74 82.34 0 top
Q17  RW1E014SNT2R_WEMT6  [SSM6K210FE_2-2N1A]  128.88 76.1 90 top
Q19  -  [TPCF8002_2-3U1A]  252.47 67.18 180 top
Q20  -  [SIS402DNT1GE_POWERPAK1212-8-5]  263.65 72.68 90 top
Q21  -  [TPCF8002_2-3U1A]  262.38 79.02 0 top
Q23  -  [TPCF8002_2-3U1A]  253.78 53.32 180 top
Q24  -  [TPCF8002_2-3U1A]  253.87 59.67 90 top
Q25  -  [2SC5658GT2LR_VMT3]  20.12 75.04 90 bottom
Q26  -  [SIS402DNT1GE_POWERPAK1212-8-5]  249.12 46.72 0 top
Q28  -  [MMBT3904_SOT23-3]  223.37 57.34 0 top
Q29  LSK3541G1ET2L 1N VMT3  [2SK3541_VMT3]  225.1 54.46 0 top
Q30  LSK3541G1ET2L 1N VMT3  [2SK3541_VMT3]  240.12 53.71 90 top
Q33  -  [TPCF8002_2-3U1A]  112.96 98.08 90 top
Q34  SIP32451DB-T2-GE1_WCSP4  [SIP32451DB-T2-GE1_WCSP_4P]  124.39 89.81 270 top
Q35  SIP32451DB-T2-GE1_WCSP4  [SIP32451DB-T2-GE1_WCSP_4P]  92.51 96.79 270 top
Q36  LSK3541G1ET2L 1N VMT3  [2SK3541_VMT3]  220.34 48.7 90 top
Q39  -  [LSK3541G1ET2L_VMT3]  97.04 57.57 270 bottom
Q40  -  [LSK3541G1ET2L_VMT3]  100.01 57.23 270 bottom
Q41  -  [RTM002P02GT2L_VMT3]  132.43 60.24 270 bottom
Q50  -  [LSK3541G1ET2L_VMT3]  284.73 52.92 90 top
Q60  -  [TPS22918DBVR_SOT23-6]  261.96 63.98 180 top
Q170  LSK3541G1ET2L 1N VMT3  [2SK3541_VMT3]  41.56 53.84 0 top
Q171  LSK3541G1ET2L 1N VMT3  [2SK3541_VMT3]  39.12 53.36 90 top
Q175  -  [DTC115EMGT2L_VMT3]  280.71 45.94 270 top
Q197  -  [LSK3541G1ET2L_VMT3]  281.82 44.95 90 top
Q199  -  [DTC115TMT2L_VMT3]  240.14 67.26 180 top
Q226  -  [LSK3541G1ET2L_VMT3]  253.81 55.42 180 top
Q227  -  [LSK3541G1ET2L_VMT3]  252.54 57.27 180 top
Q228  -  [LSK3541G1ET2L_VMT3]  284.66 56.37 0 top
Q263  -  [LSK3541G1ET2L_VMT3]  252.21 55.14 180 top
Q266  -  [TPCF8004_2-3U1S]  268.81 114.9 0 top
QA7  -  [LSK3541G1ET2L_VMT3]  277.42 45.26 180 top
QA8  -  [DTC115EMGT2L_VMT3]  284.56 48.9 0 top
QC1  DTC015TMT2L_VMT3  [DTC115TMT2L_VMT3]  60.73 52.38 180 top
QC2  LSK3541G1ET2L 1N VMT3  [2SK3541_VMT3]  74.62 94.67 90 top
QC3  LSK3541G1ET2L 1N VMT3  [2SK3541_VMT3]  69.89 94.63 90 top
R1  47_0201_5%  [R_0201]  140.72 87.23 0 bottom
R2  100_0201_5%  [R_0201]  139.08 85.84 0 bottom
R3  47K_0201_5%  [R_0201]  139.66 85.23 180 bottom
R4  47K_0201_5%  [R_0201]  142.85 87.79 0 bottom
R5  100K_0201_5%  [R_0201]  265.26 135.14 0 bottom
R6  100K_0201_5%  [R_0201]  274.44 134.97 270 top
R7  220_0201_5%  [R_0201]  276.78 136.16 90 top
R8  0_0201_5%  [R_0201]  267.17 132.75 90 bottom
R9  0_0201_5%  [R_0201]  266.58 132.75 90 bottom
R10  3.9K_0201_5%  [R_0201]  269.32 134.17 90 top
R11  0_0201_5%  [R0201_SHORT]  265.97 132.75 90 bottom
R12  0_0201_5%  [R0201_SHORT]  265.39 132.75 90 bottom
R15  100K_0201_5%  [R_0201]  274.32 138.69 270 top
R46  100K_0201_5%  [R_0201]  284.43 49.64 90 top
R51  20K_0201_5%  [R_0201]  224.41 51.6 0 top
R52  10K_0201_5%  [R_0201]  218.23 50.31 0 top
R66  10K_0201_5%  [R_0201]  282.65 55.66 90 top
R67  10K_0201_5%  [R_0201]  283.41 56.1 270 top
R89  2.7M_0201_5%  [R_0201]  275.8 84.25 90 top
R90  22.1K_0201_1%  [R_0201]  275.19 84.25 90 top
R91  4.7K_0201_5%  [R_0201]  221.97 82.51 0 top
R92  0_0201_5%  [R0201_SHORT]  207.27 72.5 0 top
R93  0_0201_5%  [R0201_SHORT]  207.43 73.55 0 top
R94  0_0201_5%  [R0201_SHORT]  224.43 86.76 0 top
R95  0_0201_5%  [R0201_SHORT]  224.43 87.4 0 top
R96  75_0805_5%  [R_0805]  278.3 131.44 0 top
R97  75_0805_5%  [R_0805]  278.3 128.64 0 top
R98  75_0805_5%  [R_0805]  278.27 122.29 0 top
R99  75_0805_5%  [R_0805]  278.27 126.1 0 top
R100  1M_0805_5%  [R_0805]  274.28 121.78 0 top
R101  10K_0201_5%  [R_0201]  226.88 59.5 270 top
R102  0_0201_5%  [R0201_SHORT]  228.03 55.27 90 top
R103  0_0201_5%  [R0201_SHORT]  228.66 55.27 90 top
R104  200_0201_1%  [R_0201]  233.35 59.45 270 top
R105  0_0201_5%  [R0201_SHORT]  202.44 56.37 90 top
R106  0_0201_5%  [R0201_SHORT]  203.03 56.37 90 top
R108  10K_0201_5%  [R_0201]  212.12 60.13 180 top
R109  10K_0201_5%  [R_0201]  273.78 84.25 90 top
R110  10K_0201_5%  [R_0201]  274.51 84.25 90 top
R111  0_0201_5%  [R_0201]  278.33 88.44 180 top
R112  10K_0201_5%  [R_0201]  285 85.1 0 top
R113  6.19K_0201_1%  [R_0201]  285.25 91.29 270 top
R116  33K_0201_5%  [R_0201]  183.69 95.6 0 top
R117  100K_0201_5%  [R_0201]  181.8 106.53 270 top
R118  100K_0201_5%  [R_0201]  180.53 105.94 90 top
R120  100K_0201_5%  [R_0201]  162.49 94.51 270 top
R124  100K_0201_5%  [R_0201]  231.83 87.38 270 top
R125  100K_0201_5%  [R_0201]  232.34 70.41 90 top
R126  10K_0201_5%  [R_0201]  240.06 81.8 0 top
R127  20K_0201_5%  [R_0201]  239.43 72.02 0 top
R128  4.7K_0201_5%  [R_0201]  234.1 69.04 270 top
R129  4.7K_0201_5%  [R_0201]  231.71 70.99 270 top
R130  10K_0201_5%  [R_0201]  228.09 85.83 270 top
R131  10K_0201_5%  [R_0201]  241.59 76.78 0 top
R132  10K_0201_5%  [R_0201]  234.51 70.39 90 top
R133  100K_0201_5%  [R_0201]  230.61 85.83 270 top
R134  10K_0201_5%  [R_0201]  239.35 77.74 0 top
R135  1K_0201_5%  [R_0201]  237.81 88.03 270 top
R136  10K_0201_5%  [R_0201]  233.51 69.04 270 top
R137  33_0201_5%  [R_0201]  225.28 79.32 180 top
R138  10K_0201_5%  [R_0201]  231.34 69.07 270 top
R139  33_0201_5%  [R_0201]  225.28 80.59 180 top
R140  100_0201_1%  [R_0201]  233.13 70.36 90 top
R142  100_0201_1%  [R_0201]  231 70.4 90 top
R143  1K_0201_5%  [R_0201]  237.18 88.03 270 top
R144  0_0402_5%  [R0402_SHORT]  223 72.35 0 top
R145  0_0402_5%  [R0402_SHORT]  221.5 73.24 0 top
R146  100K_0201_5%  [R_0201]  242.17 75.55 180 top
R147  100K_0201_5%  [R_0201]  236.8 70.97 270 top
R148  100K_0201_5%  [R_0201]  230.63 87.15 90 top
R149  100K_0201_5%  [R_0201]  235.15 70.97 270 top
R151  10K_0201_5%  [R_0201]  239.35 75.91 0 top
R152  100K_0201_5%  [R_0201]  229.41 85.25 90 top
R153  10K_0201_5%  [R_0201]  241.49 79.49 180 top
R154  100K_0201_5%  [R_0201]  231.17 85.24 90 top
R155  100K_0201_5%  [R_0201]  237.43 70.97 270 top
R156  100K_0201_5%  [R_0201]  240.83 72 0 top
R158  10K_0201_5%  [R_0201]  225.28 79.95 180 top
R159  100K_0201_5%  [R_0201]  240.12 85.11 90 top
R160  2.2K_0201_5%  [R_0201]  230.74 69.06 270 top
R161  2.2K_0201_5%  [R_0201]  231.96 69.06 270 top
R163  43_0201_5%  [R_0201]  225.28 72.71 180 top
R164  4.7K_0201_5%  [R_0201]  224.01 77.03 180 top
R165  100_0201_1%  [R_0201]  228.25 68.5 270 top
R166  1K_0201_5%  [R_0201]  223.41 77.76 90 top
R167  100_0201_1%  [R_0201]  227.67 68.5 270 top
R168  0.1U_0201_6.3V6K  [C_0201]  222.82 77.8 90 top
R169  0_0201_5%  [R0201_SHORT]  225.28 76.78 180 top
R170  4.53K_0201_1%  [R_0201]  223.34 75.02 180 top
R171  10K_0201_5%  [R_0201]  224.2 73.98 0 top
R172  10_0402_5%  [R_0402]  240.29 80.35 180 top
R173  0_0603_5%  [R0603_SHORT]  242.83 85.31 180 top
R174  0_0402_5%  [R_0402]  242.71 67.2 90 top
R175  0_0402_5%  [R_0402]  243.62 67.2 90 top
R176  1M_0201_5%  [R_0201]  239.43 73.73 0 top
R177  1M_0201_5%  [R_0201]  239.85 78.47 180 top
R178  1M_0201_5%  [R_0201]  239.43 71.44 0 top
R179  1M_0201_5%  [R_0201]  236.16 70.97 270 top
R180  1M_0201_5%  [R_0201]  241.59 74.97 0 top
R181  10K_0201_5%  [R_0201]  229.6 68.99 270 top
R182  10K_0201_5%  [R_0201]  229.03 70.39 90 top
R183  10K_0201_5%  [R_0201]  239.93 77.11 180 top
R184  10K_0201_5%  [R_0201]  230.04 85.83 270 top
R185  10K_0201_5%  [R_0201]  242.17 76.14 180 top
R186  10K_0201_5%  [R_0201]  224.61 78.17 0 top
R187  10K_0201_5%  [R_0201]  230.41 70.4 90 top
R188  4.7K_0201_5%  [R_0201]  224.89 68.21 0 top
R189  4.7K_0201_5%  [R_0201]  229.66 70.97 270 top
R192  100K_0201_5%  [R_0201]  234.17 85.74 270 top
R193  10K_0201_5%  [R_0201]  234.73 85.74 270 top
R194  10K_0201_5%  [R_0201]  237.36 85.7 270 top
R195  10K_0201_5%  [R_0201]  239.53 85.7 270 top
R196  10K_0201_5%  [R_0201]  237.94 85.71 270 top
R197  10K_0201_5%  [R_0201]  240.63 83.06 180 top
R198  10K_0201_5%  [R_0201]  240.29 81.19 180 top
R200  10K_0201_5%  [R_0201]  236.81 85.7 270 top
R201  10K_0201_5%  [R_0201]  222.28 77.14 270 top
R202  10K_0201_5%  [R_0201]  239.93 76.47 180 top
R205  10K_0201_5%  [R_0201]  228.74 85.85 270 top
R206  100K_0201_5%  [R_0201]  240.01 72.84 180 top
R207  100K_0201_5%  [R_0201]  240.01 74.37 180 top
R208  10K_0201_5%  [R_0201]  227.61 70.53 270 top
R209  10K_0201_5%  [R_0201]  226.14 70.22 270 top
R210  10K_0201_5%  [R_0201]  226.8 70.22 270 top
R211  10K_0201_5%  [R_0201]  221.34 71.83 180 top
R212  15K_0201_5%  [R_0201]  167.07 57.21 180 top
R213  15K_0201_5%  [R_0201]  177.33 63.72 90 bottom
R214  15K_0201_5%  [R_0201]  178.14 63.93 90 bottom
R215  15K_0201_5%  [R_0201]  177.66 59.74 90 bottom
R216  15K_0201_5%  [R_0201]  178.27 59.74 90 bottom
R217  15K_0201_5%  [R_0201]  178.98 59.74 90 bottom
R218  15K_0201_5%  [R_0201]  180.02 59.75 90 bottom
R219  15K_0201_5%  [R_0201]  181.01 61 90 bottom
R220  4.7K_0201_5%  [R_0201]  138.07 57.12 90 bottom
R221  4.7K_0201_5%  [R_0201]  136.43 57.11 90 bottom
R222  10K_0201_5%  [R_0201]  137.07 57.11 90 bottom
R223  680_0402_5%  [R_0402]  162.43 59.68 180 top
R224  680_0402_5%  [R_0402]  162.49 56.55 90 top
R225  100_0402_5%  [R_0402]  165.25 59.94 180 top
R226  4.7K_0201_5%  [R_0201]  167.46 62.6 180 top
R227  4.7K_0201_5%  [R_0201]  168.22 61.05 180 top
R230  100K_0201_5%  [R_0201]  136.84 64.13 0 top
R231  100_0201_5%  [R_0201]  163.62 63.28 180 bottom
R232  47K_0201_5%  [R_0201]  166.63 64.6 0 top
R233  1K_0201_5%  [R_0201]  166 64.6 180 top
R234  10K_0201_5%  [R_0201]  173.39 88.42 0 top
R235  10K_0201_5%  [R_0201]  173.39 89.01 0 top
R236  10K_0201_5%  [R_0201]  173.97 87.84 180 top
R237  0_0603_5%  [R0603_SHORT]  135.54 61.3 270 top
R238  10K_0201_5%  [R_0201]  134.2 57.92 180 top
R239  10K_0201_5%  [R_0201]  133.56 61.63 270 top
R240  33_0201_5%  [R_0201]  134.2 58.51 180 top
R241  33_0201_5%  [R_0201]  134.02 57.34 180 top
R242  33_0201_5%  [R_0201]  134.12 59.17 180 top
R243  33_0201_5%  [R_0201]  123.86 72.9 270 top
R244  0_0201_5%  [R0201_SHORT]  263.56 129.12 0 top
R245  0_0201_5%  [R0201_SHORT]  263.54 128.43 0 top
R246  0_0201_5%  [R0201_SHORT]  263.54 127.79 0 top
R247  0_0201_5%  [R0201_SHORT]  263.54 127.16 0 top
R248  10K_0201_5%  [R_0201]  244.1 94.19 270 top
R249  10K_0201_5%  [R_0201]  250.58 95.2 0 top
R251  10K_0201_5%  [R_0201]  250.58 95.84 0 top
R252  10K_0201_5%  [R_0201]  244.74 94.19 270 top
R254  47K_0201_5%  [R_0201]  249.56 83.86 270 top
R255  10K_0201_5%  [R_0201]  244.02 80.24 180 top
R256  100K_0201_5%  [R_0201]  246.05 73.77 180 top
R257  100K_0201_5%  [R_0201]  246.05 73.13 180 top
R258  100K_0201_5%  [R_0201]  250.46 70.88 270 top
R259  100K_0201_5%  [R_0201]  248.12 71.01 180 top
R260  0_0201_5%  [R0201_SHORT]  251.75 84 90 top
R261  33_0201_5%  [R_0201]  246.14 80.59 90 top
R262  33_0201_5%  [R_0201]  247.03 81.6 90 top
R263  33_0201_5%  [R_0201]  246.18 78.72 180 top
R264  0_0201_5%  [R_0201]  247.66 81.6 90 top
R265  100K_0201_5%  [R_0201]  248.93 82.19 270 top
R266  100K_0201_5%  [R_0201]  248.3 82.19 270 top
R268  100K_0201_5%  [R_0201]  245.59 79.35 0 top
R269  100K_0201_5%  [R_0201]  245.59 78.08 0 top
R270  10K_0201_5%  [R_0201]  244.07 78.55 180 top
R271  4.7K_0201_5%  [R_0201]  245.59 76.81 0 top
R273  10_0603_5%  [R_0603]  256.74 77.53 0 top
R274  20_0603_5%_ESR03EZPJ200  [R_0603]  258.59 80.43 90 top
R275  20_0603_5%_ESR03EZPJ200  [R_0603]  259.86 80.43 90 top
R276  1.78M_0402_1%  [R_0402]  259.47 78.64 90 top
R277  100_0402_5%  [R_0402]  267.04 81.44 0 top
R278  0_0402_5%  [R0402_SHORT]  257.65 78.64 180 top
R279  1.24M_0402_1%  [R_0402]  258.59 79.56 270 top
R280  100K_0201_5%  [R_0201]  254.78 81.56 90 top
R281  20_0603_5%_ESR03EZPJ200  [R_0603]  256.09 82.47 270 top
R283  33K_0201_5%  [R_0201]  246.05 74.4 180 top
R284  2K_0201_5%  [R_0201]  246.05 72.32 180 top
R285  10K_0201_5%  [R_0201]  244.15 75.04 180 top
R286  0_0201_5%  [R_0201]  246.05 75.11 180 top
R288  33K_0201_5%  [R_0201]  243.54 73.44 0 top
R289  0_0201_5%  [R_0201]  244.12 74.07 180 top
R290  100_0201_5%  [R_0201]  128.49 77.88 0 top
R292  33_0201_5%  [R_0201]  127.87 77.88 180 top
R294  33_0201_5%  [R_0201]  249.48 66.28 270 top
R295  100_0201_5%  [R_0201]  249.47 66.9 90 top
R296  270_0201_5%  [R_0201]  265.27 74 180 top
R297  100_0201_5%  [R_0201]  265.34 79.53 270 top
R299  100_0201_5%  [R_0201]  265.27 74.61 180 top
R301  100_0201_5%  [R_0201]  264.54 78.12 180 top
R302  0.01_0603_LE_1%  [R_0603_LE]  250.73 61.54 270 top
R303  33_0201_5%  [R_0201]  250.86 53.54 270 top
R304  0_0603_5%  [R0603_SHORT]  134.3 57.04 180 bottom
R305  100_0201_5%  [R_0201]  251.03 54.14 90 top
R306  100_0201_5%  [R_0201]  253.71 62.73 0 top
R307  0_0402_5%  [R_0402]  243.42 69.1 90 top
R309  0_0201_5%  [R_0201]  18.26 33.62 180 top
R310  0_0201_5%  [R_0201]  18.26 33.01 180 top
R311  0_0201_5%  [R_0201]  18.26 29.58 180 top
R312  0_0201_5%  [R_0201]  31.93 44.19 90 top
R313  0_0201_5%  [R_0201]  18.26 30.19 180 top
R314  20K_0201_5%  [R_0201]  12.26 40.22 180 top
R315  113_0402_1%  [R_0402]  279.69 59.42 180 top
R316  0_0201_5%  [R_0201]  18.32 31.51 180 top
R317  113_0402_1%  [R_0402]  279.63 60.82 180 top
R318  0_0201_5%  [R_0201]  18.32 32.12 180 top
R319  100K_0402_1%  [R_0402]  280.62 44.67 180 top
R320  0_0201_5%  [R_0201]  18.29 28.69 180 top
R322  10K_0201_5%  [R_0201]  247.47 56.38 90 top
R323  0_0201_5%  [R_0201]  18.29 28.08 180 top
R324  0_0402_5%  [R_0402]  259.95 68.57 270 top
R325  0_0402_5%  [R_0402]  260.81 68.57 270 top
R340  2.2K_0201_5%  [R_0201]  14.65 32.93 0 bottom
R341  2.2K_0201_5%  [R_0201]  14.65 32.35 0 bottom
R342  4.7K_0201_5%  [R_0201]  239.54 51.79 0 top
R343  4.7K_0201_5%  [R_0201]  235.37 49.19 180 top
R344  4.7K_0201_5%  [R_0201]  240.17 49.99 270 top
R345  4.7K_0201_5%  [R_0201]  235.37 48.61 180 top
R346  4.7K_0201_5%  [R_0201]  240.12 51.23 180 top
R347  4.7K_0201_5%  [R_0201]  234.78 49.77 0 top
R348  4.7K_0201_5%  [R_0201]  240.13 50.66 180 top
R349  4.7K_0201_5%  [R_0201]  235.71 47.07 90 top
R350  10K_0201_5%  [R_0201]  236.02 85.12 90 top
R351  4.7K_0201_5%  [R_0201]  227.95 50 0 top
R352  4.7K_0201_5%  [R_0201]  235.36 50.39 180 top
R353  10K_0201_5%  [R_0201]  235.87 86.92 270 top
R354  0_0603_5%  [R_0603]  228.79 53.56 270 top
R355  0_0603_5%  [R0603_SHORT]  239.81 47.23 90 top
R356  4.7K_0201_5%  [R_0201]  232.91 50.61 0 top
R357  4.7K_0201_5%  [R_0201]  228.53 49.42 180 top
R358  4.7K_0201_5%  [R_0201]  232.93 48.88 0 top
R359  4.7K_0201_5%  [R_0201]  229.03 47.63 270 top
R360  4.7K_0201_5%  [R_0201]  233.5 50.02 180 top
R361  4.7K_0201_5%  [R_0201]  227.95 48.81 0 top
R362  4.7K_0201_5%  [R_0201]  233.51 49.44 180 top
R363  4.7K_0201_5%  [R_0201]  227.95 48.22 0 top
R365  4.7K_0201_5%  [R_0201]  232.91 51.19 0 top
R368  100K_0201_5%  [R_0201]  199.22 58.11 270 top
R369  100K_0201_5%  [R_0201]  199.22 59.28 270 top
R370  10K_0201_5%  [R_0201]  208.96 51.5 180 top
R372  47_0201_5%  [R_0201]  250.44 45.55 0 top
R373  100_0201_5%  [R_0201]  253.01 46.72 180 top
R374  100K_0201_5%  [R_0201]  224.57 75 0 top
R375  100K_0201_5%  [R_0201]  224.64 70.89 0 top
R376  10K_0201_5%  [R_0201]  127.54 57.99 90 bottom
R377  20K_0201_5%  [R_0201]  224.99 51.02 180 top
R382  10K_0201_5%  [R_0201]  246.62 82.97 90 top
R383  4.7K_0201_5%  [R_0201]  226.37 52.17 90 top
R384  0_0805_5%  [R0805_SHORT]  248.59 51.78 0 top
R385  0_0805_5%  [R0805_SHORT]  247.37 61.33 0 top
R387  0_0805_5%  [R0805_SHORT]  268.22 80.07 180 top
R389  100_0201_5%  [R_0201]  112.76 101.05 0 top
R390  270_0201_5%  [R_0201]  111.01 103.49 180 top
R392  75_0201_1%  [R_0201]  242.5 69 180 top
R393  0_0201_5%  [R0201_SHORT]  238.03 70.38 90 top
R394  10K_0201_5%  [R_0201]  140.48 65.42 180 bottom
R395  0_0603_5%  [R_0603]  221.36 68.89 180 top
R396  0_0201_5%  [R0201_SHORT]  134.03 56.71 180 top
R397  10K_0201_5%  [R_0201]  134.03 56.1 180 top
R398  10K_0201_5%  [R_0201]  90.48 97.56 90 top
R399  10K_0201_5%  [R_0201]  91.34 96.89 270 top
R401  100K_0201_5%  [R_0201]  139.9 64.1 180 top
R402  10K_0201_5%  [R_0201]  239.26 79.03 0 top
R403  10K_0201_5%  [R_0201]  235.16 68.4 90 top
R404  10K_0201_5%  [R_0201]  239.26 79.62 0 top
R405  10K_0201_5%  [R_0201]  247.68 86.91 270 top
R406  0_0201_5%  [R_0201]  113.33 102.2 180 top
R407  0_0201_5%  [R_0201]  113.33 101.64 180 top
R408  0_0201_5%  [R_0201]  241.3 54.8 180 top
R409  4.7K_0201_5%  [R_0201]  220.01 50.08 180 top
R413  10K_0201_5%  [R_0201]  227.49 85.83 270 top
R414  0_0201_5%  [R_0201]  260.88 102.33 270 top
R415  0_0201_5%  [R_0201]  229.6 47.04 90 top
R416  0_0201_5%  [R_0201]  230.16 47.04 90 top
R423  0_0201_5%  [R_0201]  238.21 61.38 90 top
R424  0_0201_5%  [R_0201]  238.85 61.38 90 top
R425  0_0201_5%  [R_0201]  239.48 61.38 90 top
R426  0_0201_5%  [R_0201]  219.08 53.57 270 top
R427  1M_0201_5%  [R_0201]  100.56 58.49 0 bottom
R428  10K_0201_5%  [R_0201]  131.8 60.97 180 bottom
R430  0_0201_5%  [R_0201]  241.39 72.73 90 top
R431  0_0402_5%  [R_0402]  114.16 96.71 180 bottom
R433  0_0201_5%  [R_0201]  221.95 52.18 0 bottom
R434  100_0201_1%  [R_0201]  132.06 59.44 270 bottom
R435  0_0201_5%  [R_0201]  217.89 46.65 180 top
R436  100K_0201_5%  [R_0201]  248.29 69.14 90 top
R437  0_0201_5%  [R0201_SHORT]  254.97 84.43 90 top
R439  10K_0402_5%  [R_0402]  17.43 49.39 270 top
R440  100K_0201_5%  [R_0201]  240.05 82.49 0 top
R441  0_0402_5%  [R0402_SHORT]  32.29 51.75 180 top
R443  0_0402_5%  [R_0402]  127.57 59.3 90 bottom
R450  10K_0402_5%  [R_0402]  5.49 64.56 180 top
R457  10K_0201_5%  [R_0201]  123.24 89.32 90 top
R458  5.1K_0402_1%  [R_0402]  124 90.67 180 top
R460  2.2K_0201_5%  [R_0201]  284.74 64.92 90 top
R461  0_0201_5%  [R0201_SHORT]  167.62 65.82 90 bottom
R462  0_0201_5%  [R0201_SHORT]  167.03 65.82 90 bottom
R483  10K_0402_5%  [R_0402]  33.38 48.35 90 top
R484  1M_0402_5%  [R_0402]  279.87 65.16 90 top
R485  10K_0201_5%  [R_0201]  39.64 52.26 0 top
R486  10K_0201_5%  [R_0201]  112.96 76.42 180 bottom
R489  0_0402_5%  [R_0402]  21.01 63.49 0 top
R490  10K_0402_5%  [R_0402]  222.08 80.71 90 top
R508  1M_0402_5%  [R_0402]  5.46 62.7 90 top
R509  51.1K_0402_1%  [R_0402]  4.6 62.7 90 top
R532  4.7K_0402_5%  [R_0402]  47.81 74.79 90 top
R537  0_0201_5%  [R_0201]  285.54 64.86 0 top
R546  0_0201_5%  [R_0201]  233.15 54.68 270 top
R547  0_0201_5%  [R_0201]  232.59 54.68 270 top
R571  0_0402_5%  [R_0402]  26.35 44.11 90 top
R572  0_0402_5%  [R_0402]  34.82 52.44 90 top
R573  0_0402_5%  [R0402_SHORT]  26.39 42.1 180 top
R574  0_0402_5%  [R_0402]  34.93 54.45 180 top
R576  0_0402_5%  [R_0402]  25.49 44.11 90 top
R600  10K_0201_5%  [R_0201]  234.82 56.7 270 top
R601  10K_0201_5%  [R_0201]  236.03 54.6 180 top
R602  0_0201_5%  [R_0201]  253.07 54.7 0 top
R677  33_0402_5%  [R_0402]  269.35 69.91 90 top
R678  4.7K_0402_5%  [R_0402]  22.43 64.81 90 bottom
R679  0_0402_5%  [R_0402]  29.72 66.97 0 top
R680  4.7K_0402_5%  [R_0402]  29.69 68.11 0 top
R681  4.7K_0402_5%  [R_0402]  25.86 74.79 90 bottom
R682  0_0402_5%  [R_0402]  24.08 75.2 0 bottom
R702  10K_0201_5%  [R_0201]  30.7 55.67 0 top
R703  10K_0201_5%  [R_0201]  30.75 54.65 0 top
R707  0_0402_5%  [R0402_SHORT]  20.55 49.5 270 top
R708  0_0402_5%  [R0402_SHORT]  20.55 47.74 270 top
R711  10K_0402_5%  [R_0402]  21.92 62.6 180 top
R712  10K_0402_5%  [R_0402]  34.85 61.56 90 top
R713  3.3K_0402_1%  [R_0402]  33.92 61.84 180 top
R714  3.3K_0402_1%  [R_0402]  33.92 60.9 180 top
R715  3.3K_0402_1%  [R_0402]  32.49 58.19 270 top
R716  3.3K_0402_1%  [R_0402]  21.36 59.88 0 top
R721  1M_0402_5%  [R_0402]  28.46 44.11 90 top
R722  1M_0402_5%  [R_0402]  30.27 44.11 90 top
R723  1M_0402_5%  [R_0402]  31.16 44.11 90 top
R724  1M_0402_5%  [R_0402]  27.56 44.11 90 top
R725  0_0201_5%  [R0201_SHORT]  29.06 41.66 90 top
R727  100K_0402_5%  [R_0402]  28.94 56.07 270 top
R728  1M_0402_5%  [R_0402]  29.34 45.03 270 top
R729  100K_0402_5%  [R_0402]  19.72 50.66 0 top
R742  220_0201_5%  [R_0201]  286.5 56.48 180 bottom
R743  220_0201_5%  [R_0201]  285.79 54.42 0 bottom
R780  100K_0402_5%  [R_0402]  19.72 52.41 0 top
R781  100K_0402_5%  [R_0402]  19.72 51.52 0 top
R782  100K_0402_5%  [R_0402]  27.26 42.13 270 top
R783  100K_0402_5%  [R_0402]  28.15 42.13 270 top
R784  15K_0402_0.1%  [R_0402]  27.21 55.16 90 top
R785  1M_0402_5%  [R_0402]  20.63 53.3 180 top
R786  1M_0402_5%  [R_0402]  20.63 54.19 180 top
R789  0_0201_5%  [R_0201]  234.06 58.84 0 top
R790  100K_0402_5%  [R_0402]  21.98 55.74 270 top
R791  100K_0402_5%  [R_0402]  19.72 55.97 0 top
R798  10K_0201_5%  [R_0201]  238.62 85.11 90 top
R799  1M_0402_5%  [R_0402]  32.29 48.18 180 top
R801  0_0402_5%  [R_0402]  32.51 49.12 180 top
R802  0_0201_5%  [R_0201]  39.05 52.26 180 top
R819  0_0402_5%  [R_0402]  28.08 56.07 270 top
R849  10K_0402_5%  [R_0402]  224.29 81.55 0 top
R850  100K_0402_5%  [R_0402]  224.29 84.16 0 top
R851  4.7K_0402_5%  [R_0402]  225.21 83.3 180 top
R852  4.7K_0402_5%  [R_0402]  225.21 82.41 180 top
R862  0_0402_5%  [R_0402]  34.67 49.27 270 top
R904  0_0201_5%  [R_0201]  140.69 62.1 90 bottom
